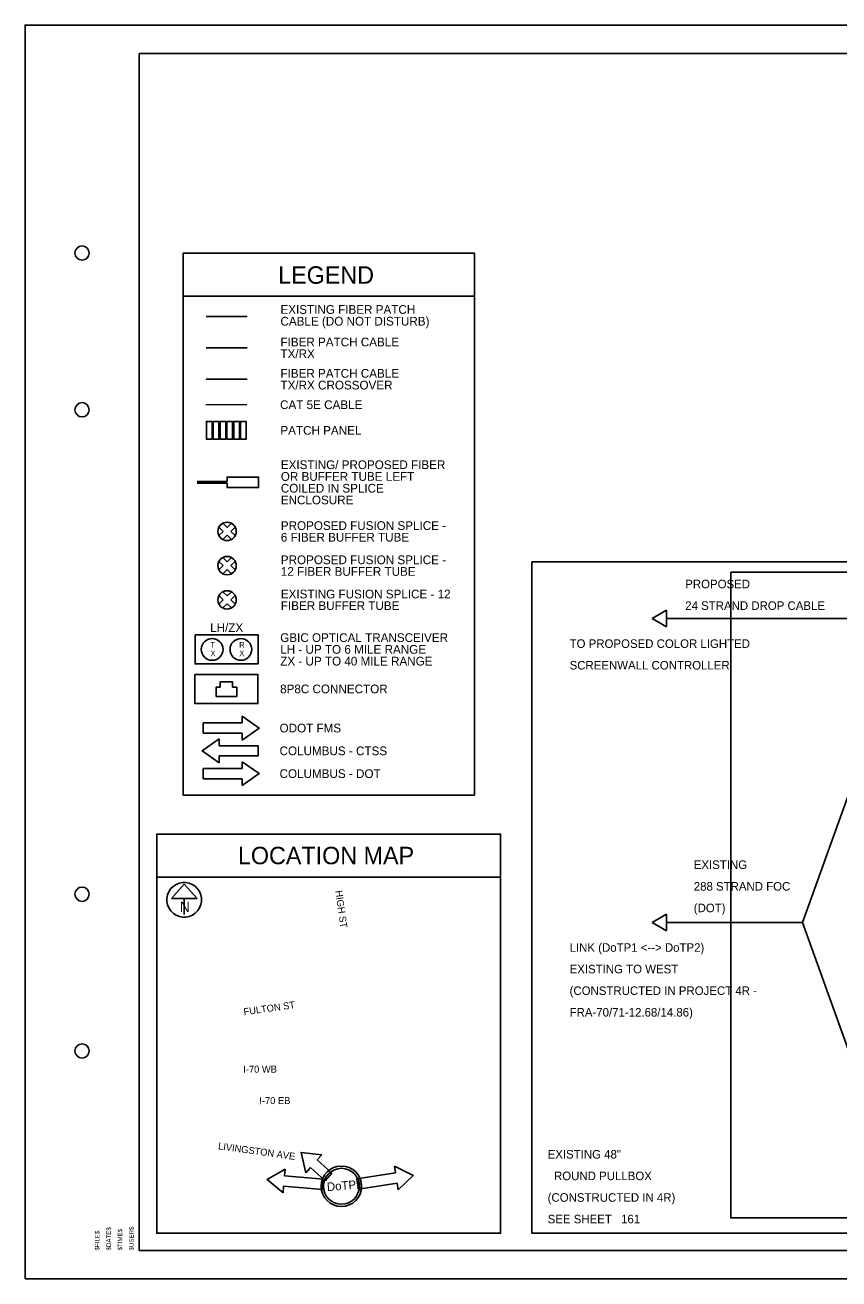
# Model space of a CAD drawing. Extents: x 1805893 to 1833564, y 708898 to 716199.
# Drawn here: x 1831322.5 to 1831608.1, y 714257.9 to 714697.9 of the extents above; entities that cross this region are included whole.
import ezdxf

# ---------------------------------------------------------------- set-up
doc = ezdxf.new("R2010")
doc.units = 0
for name, color, linetype in [('BR_P_Sub_Hidden', 7, 'Continuous'), ('BR_X_Slab_Object', 7, 'Continuous'), ('SH_Border', 7, 'Continuous'), ('SH_Cut_Line', 7, 'Continuous'), ('SH_Data', 7, 'Continuous'), ('SH_Text', 7, 'Continuous'), ('UT_X_Misc_Cells', 7, 'Continuous')]:
    doc.layers.add(name, color=color, linetype=linetype)

msp = doc.modelspace()

# ---------------------------------------------------------------- linework, layer by layer
at = {"layer": 'BR_P_Sub_Hidden'}
for points in [[(1831500.32, 714509.57), (1831957.51, 714509.57), (1831957.51, 714273.91), (1831500.32, 714273.91)], [(1831570.12, 714505.91), (1831894.14, 714505.91), (1831894.14, 714279.3), (1831570.12, 714279.3)]]:
    msp.add_lwpolyline(points, close=True, dxfattribs=at)
at = {"layer": 'SH_Border'}
msp.add_lwpolyline([(1831362.49, 714687.91), (1831992.49, 714687.91), (1831992.49, 714267.91), (1831362.49, 714267.91)], close=True, dxfattribs=at)
for centre in [(1831342.49, 714617.91), (1831342.49, 714562.91), (1831342.49, 714392.91), (1831342.49, 714337.91)]:
    msp.add_circle(centre, 2.5, dxfattribs=at)
at = {"layer": 'SH_Cut_Line'}
msp.add_lwpolyline([(1831322.49, 714257.91), (1832002.49, 714257.91), (1832002.49, 714697.91), (1831322.49, 714697.91)], close=True, dxfattribs=at)
at = {"layer": 'SH_Data'}
for p, q in [((1831386.09, 714595.63), (1831400.43, 714595.63)), ((1831386.09, 714584.63), (1831400.43, 714584.63)), ((1831392.03, 714520.23), (1831390.54, 714521.72)), ((1831390.54, 714521.72), (1831392.03, 714520.23)), ((1831393.39, 714521.58), (1831391.9, 714523.08)), ((1831393.39, 714521.58), (1831391.9, 714523.08)), ((1831393.39, 714521.58), (1831394.88, 714523.08)), ((1831394.88, 714523.08), (1831393.39, 714521.58)), ((1831394.75, 714520.23), (1831396.24, 714521.72)), ((1831394.75, 714520.23), (1831396.24, 714521.72)), ((1831390.54, 714518.74), (1831392.03, 714520.23)), ((1831392.03, 714520.23), (1831390.54, 714518.74)), ((1831391.9, 714517.38), (1831393.39, 714518.87)), ((1831391.9, 714517.38), (1831393.39, 714518.87)), ((1831394.88, 714517.38), (1831393.39, 714518.87)), ((1831393.39, 714518.87), (1831394.88, 714517.38)), ((1831396.24, 714518.74), (1831394.75, 714520.23)), ((1831396.24, 714518.74), (1831394.75, 714520.23)), ((1831392.03, 714508.22), (1831390.54, 714509.71)), ((1831392.03, 714508.22), (1831390.54, 714509.71)), ((1831390.54, 714506.73), (1831392.03, 714508.22)), ((1831390.54, 714506.73), (1831392.03, 714508.22)), ((1831393.39, 714509.57), (1831391.9, 714511.07)), ((1831391.9, 714511.07), (1831393.39, 714509.57)), ((1831393.39, 714509.57), (1831394.88, 714511.07)), ((1831393.39, 714509.57), (1831394.88, 714511.07)), ((1831394.75, 714508.22), (1831396.24, 714509.71)), ((1831396.24, 714509.71), (1831394.75, 714508.22)), ((1831396.24, 714506.73), (1831394.75, 714508.22)), ((1831394.75, 714508.22), (1831396.24, 714506.73)), ((1831391.9, 714505.37), (1831393.39, 714506.86)), ((1831393.39, 714506.86), (1831391.9, 714505.37)), ((1831394.88, 714505.37), (1831393.39, 714506.86)), ((1831394.88, 714505.37), (1831393.39, 714506.86)), ((1831393.39, 714497.57), (1831391.9, 714499.06)), ((1831391.9, 714499.06), (1831393.39, 714497.57)), ((1831393.39, 714497.57), (1831394.88, 714499.06)), ((1831393.39, 714497.57), (1831394.88, 714499.06)), ((1831392.03, 714496.21), (1831390.54, 714497.71)), ((1831392.03, 714496.21), (1831390.54, 714497.71)), ((1831390.54, 714494.72), (1831392.03, 714496.21)), ((1831390.54, 714494.72), (1831392.03, 714496.21)), ((1831391.9, 714493.37), (1831393.39, 714494.86)), ((1831393.39, 714494.86), (1831391.9, 714493.37)), ((1831394.88, 714493.37), (1831393.39, 714494.86)), ((1831394.88, 714493.37), (1831393.39, 714494.86)), ((1831394.75, 714496.21), (1831396.24, 714497.71)), ((1831396.24, 714497.71), (1831394.75, 714496.21)), ((1831396.24, 714494.72), (1831394.75, 714496.21)), ((1831394.75, 714496.21), (1831396.24, 714494.72)), ((1831542.51, 714489.68), (1831547.53, 714492.58)), ((1831547.53, 714486.78), (1831542.51, 714489.68)), ((1831547.53, 714492.58), (1831547.53, 714486.78)), ((1831613.14, 714489.68), (1831547.53, 714489.68)), ((1831398.67, 714453.02), (1831398.67, 714455.42)), ((1831384.93, 714453.02), (1831398.67, 714453.02)), ((1831384.93, 714449.42), (1831384.93, 714453.02)), ((1831398.67, 714449.42), (1831384.93, 714449.42)), ((1831390.6, 714447.42), (1831390.6, 714445.02)), ((1831398.67, 714447.02), (1831398.67, 714449.42)), ((1831390.6, 714445.02), (1831404.34, 714445.02)), ((1831404.34, 714441.42), (1831390.6, 714441.42)), ((1831390.6, 714441.42), (1831390.6, 714439.02)), ((1831404.34, 714445.02), (1831404.34, 714441.42)), ((1831384.93, 714437.02), (1831398.67, 714437.02)), ((1831384.93, 714433.42), (1831384.93, 714437.02)), ((1831398.67, 714437.02), (1831398.67, 714439.42)), ((1831398.67, 714433.42), (1831384.93, 714433.42)), ((1831398.67, 714431.02), (1831398.67, 714433.42)), ((1831547.53, 714385.89), (1831542.51, 714382.99)), ((1831547.53, 714380.09), (1831547.53, 714385.89)), ((1831542.51, 714382.99), (1831547.53, 714380.09)), ((1831595.29, 714382.99), (1831547.53, 714382.99))]:
    msp.add_line(p, q, dxfattribs=at)
for points in [[(1831377.93, 714617.86), (1831480.16, 714617.86), (1831480.16, 714602.75), (1831377.93, 714602.75)], [(1831480.16, 714617.86), (1831480.16, 714427.7), (1831377.93, 714427.7), (1831377.93, 714617.86)], [(1831388.1, 714558.81), (1831388.1, 714552.56), (1831386.14, 714552.56), (1831386.14, 714558.81)], [(1831390.49, 714558.81), (1831390.49, 714552.56), (1831388.53, 714552.56), (1831388.53, 714558.81)], [(1831392.89, 714558.81), (1831392.89, 714552.56), (1831390.93, 714552.56), (1831390.93, 714558.81)], [(1831395.28, 714558.81), (1831395.28, 714552.56), (1831393.32, 714552.56), (1831393.32, 714558.81)], [(1831397.68, 714558.81), (1831397.68, 714552.56), (1831395.72, 714552.56), (1831395.72, 714558.81)], [(1831400.07, 714558.81), (1831400.07, 714552.56), (1831398.11, 714552.56), (1831398.11, 714558.81)], [(1831382.14, 714483.95), (1831404.23, 714483.95), (1831404.23, 714473.7), (1831382.14, 714473.7)], [(1831382.08, 714470.07), (1831404.18, 714470.07), (1831404.18, 714459.82), (1831382.08, 714459.82)], [(1831489.36, 714414.04), (1831368.72, 714414.04), (1831368.72, 714398.93), (1831489.36, 714398.93)], [(1831489.36, 714398.93), (1831368.72, 714398.93), (1831368.72, 714414.04), (1831489.36, 714414.04)], [(1831489.36, 714398.93), (1831489.36, 714273.91), (1831368.72, 714273.91), (1831368.72, 714398.93)], [(1831489.36, 714398.93), (1831489.36, 714273.91), (1831368.72, 714273.91), (1831368.72, 714398.93)], [(1831489.36, 714398.93), (1831489.36, 714273.91), (1831368.72, 714273.91), (1831368.72, 714398.93)]]:
    msp.add_lwpolyline(points, close=True, dxfattribs=at)
for points in [[(1831400.46, 714573.63), (1831386.09, 714573.63), (1831386.09, 714573.63), (1831386.09, 714573.63)], [(1831385.95, 714564.69), (1831400.29, 714564.72), (1831400.29, 714564.72)], [(1831383.09, 714537.75), (1831383.09, 714537.45), (1831383.09, 714537.14), (1831393.38, 714537.14), (1831393.38, 714535.61), (1831404.43, 714535.61), (1831404.43, 714539.28), (1831393.38, 714539.28), (1831393.38, 714537.75), (1831383.09, 714537.75)], [(1831404.43, 714535.61), (1831404.43, 714539.28), (1831393.38, 714539.28), (1831393.38, 714537.75), (1831383.09, 714537.75), (1831383.09, 714537.45), (1831383.09, 714537.14), (1831393.38, 714537.14), (1831393.38, 714535.61), (1831404.43, 714535.61)], [(1831395.25, 714465.55), (1831396.76, 714465.55), (1831396.76, 714462.32), (1831389.49, 714462.32), (1831389.49, 714465.55), (1831391, 714465.55)], [(1831391, 714465.55), (1831391, 714467.46), (1831395.25, 714467.46), (1831395.25, 714465.55)], [(1831624.88, 714465.18), (1831595.29, 714382.99), (1831624.88, 714300.79)], [(1831624.88, 714465.18), (1831595.29, 714382.99), (1831624.88, 714300.79)], [(1831398.67, 714455.42), (1831404.67, 714451.22), (1831398.67, 714447.02)], [(1831390.6, 714439.02), (1831384.6, 714443.22), (1831390.6, 714447.42)], [(1831398.67, 714439.42), (1831404.67, 714435.22), (1831398.67, 714431.02)]]:
    msp.add_lwpolyline(points, dxfattribs=at)
for centre, radius in [((1831393.39, 714520.23), 3.22), ((1831393.39, 714508.22), 3.22), ((1831393.39, 714496.21), 3.22), ((1831388.14, 714478.83), 3.81), ((1831398.23, 714478.83), 3.81)]:
    msp.add_circle(centre, radius, dxfattribs=at)
for centre, start, end in [((1831393.39, 714520.23), 117.647, 152.353), ((1831393.39, 714520.23), 27.647, 62.353), ((1831393.39, 714520.23), 207.647, 242.353), ((1831393.39, 714520.23), 297.647, 332.353), ((1831393.39, 714508.22), 152.353, 207.647), ((1831393.39, 714508.22), 62.353, 117.647), ((1831393.39, 714508.22), 332.353, 27.647), ((1831393.39, 714508.22), 242.353, 297.647), ((1831393.39, 714496.21), 62.353, 117.647), ((1831393.39, 714496.21), 152.353, 207.647), ((1831393.39, 714496.21), 332.353, 27.647), ((1831393.39, 714496.21), 242.353, 297.647)]:
    msp.add_arc(centre, 3.22, start, end, dxfattribs=at)
at = {"layer": 'SH_Text'}
for p, q in [((1831378.33, 714396.42), (1831373.82, 714391.42)), ((1831382.83, 714391.42), (1831378.33, 714396.42)), ((1831373.82, 714391.42), (1831382.83, 714391.42)), ((1831378.33, 714391.42), (1831378.33, 714385.76)), ((1831426.62, 714301.44), (1831425.02, 714299.65)), ((1831413.75, 714296.47), (1831413.54, 714294.08)), ((1831422.63, 714296.96), (1831421.03, 714295.17)), ((1831427.76, 714292.39), (1831422.63, 714296.96)), ((1831425.02, 714299.65), (1831430.15, 714295.08)), ((1831452.52, 714295.12), (1831452.16, 714297.49)), ((1831413.54, 714294.08), (1831427.22, 714292.87)), ((1831427.22, 714292.87), (1831426.9, 714289.28)), ((1831430.15, 714295.08), (1831427.76, 714292.39)), ((1831438.95, 714293.01), (1831452.52, 714295.12)), ((1831439.5, 714289.46), (1831438.95, 714293.01)), ((1831413.22, 714290.49), (1831413.01, 714288.1)), ((1831426.9, 714289.28), (1831413.22, 714290.49)), ((1831453.08, 714291.56), (1831439.5, 714289.46)), ((1831453.44, 714289.19), (1831453.08, 714291.56))]:
    msp.add_line(p, q, dxfattribs=at)
for points in [[(1831421.03, 714295.17), (1831419.34, 714302.29), (1831426.62, 714301.44)], [(1831413.01, 714288.1), (1831407.4, 714292.82), (1831413.75, 714296.47)], [(1831452.16, 714297.49), (1831458.73, 714294.26), (1831453.44, 714289.19)]]:
    msp.add_lwpolyline(points, dxfattribs=at)
for radius in [7.11, 6.31]:
    msp.add_circle((1831433.49, 714290.41), radius, dxfattribs=at)
msp.add_arc((1831378.33, 714390.95), 6.08, 129.7798, 129.7633, dxfattribs=at)

# ---------------------------------------------------------------- texts
at = {"layer": 'BR_X_Slab_Object'}
for s, p in [('T', (1831387.53, 714479.43)), ('R', (1831397.63, 714479.43)), ('X', (1831387.53, 714476.43)), ('X', (1831397.63, 714476.43))]:
    msp.add_text(s, height=2, rotation=0.0475, dxfattribs=at).set_placement(p)
msp.add_text('161', height=3, dxfattribs=at).set_placement((1831531.63, 714277.41))
at = {"layer": 'SH_Data'}
for s, height, p in [('LEGEND', 6.119, (1831411.3, 714607.14)), ('EXISTING FIBER PATCH ', 3.0596, (1831412.11, 714596.58)), ('CABLE (DO NOT DISTURB)', 3.0596, (1831412.11, 714592.46)), ('FIBER PATCH CABLE', 3.0596, (1831412.11, 714585.16)), ('TX/RX', 3.06, (1831412.11, 714581.04)), ('TX/RX CROSSOVER', 3.0596, (1831412.11, 714570.04)), ('FIBER PATCH CABLE', 3.0596, (1831412.11, 714574.16)), ('CAT 5E CABLE', 3.0596, (1831411.97, 714563.16)), ('PATCH PANEL', 3.0596, (1831412.09, 714554.16)), ('EXISTING/ PROPOSED FIBER ', 3.0596, (1831412.23, 714542.1)), ('OR BUFFER TUBE LEFT ', 3.0596, (1831412.23, 714537.98)), ('COILED IN SPLICE ', 3.0596, (1831412.23, 714533.85)), ('ENCLOSURE', 3.06, (1831412.23, 714529.73)), ('PROPOSED FUSION SPLICE - ', 3.0596, (1831412.24, 714520.74)), ('6 FIBER BUFFER TUBE', 3.0596, (1831412.24, 714516.66)), ('PROPOSED FUSION SPLICE - ', 3.0596, (1831412.24, 714508.73)), ('12 FIBER BUFFER TUBE', 3.0596, (1831412.24, 714504.65)), ('PROPOSED', 3, (1831554.15, 714500.26)), ('EXISTING FUSION SPLICE - 12 ', 3.0596, (1831412.24, 714496.72)), ('FIBER BUFFER TUBE', 3.0596, (1831412.24, 714492.65)), ('24 STRAND DROP CABLE', 3, (1831554.15, 714492.68)), ('LH/ZX', 3.06, (1831387.45, 714484.95)), ('GBIC OPTICAL TRANSCEIVER', 3.0596, (1831412.03, 714481.42)), ('TO PROPOSED COLOR LIGHTED', 3, (1831513.57, 714479.35)), ('LH - UP TO 6 MILE RANGE', 3.0596, (1831412.03, 714477.3)), ('ZX - UP TO 40 MILE RANGE', 3.0596, (1831412.03, 714473.17)), ('SCREENWALL CONTROLLER', 3, (1831513.57, 714471.77)), ('8P8C CONNECTOR', 3.0596, (1831411.98, 714463.42)), ('ODOT FMS', 3.06, (1831411.8, 714449.69)), ('COLUMBUS - CTSS', 3.0596, (1831411.8, 714441.69)), ('COLUMBUS - DOT', 3.0596, (1831411.8, 714433.69)), ('LOCATION MAP', 6.1191, (1831397.18, 714403.43)), ('EXISTING', 3, (1831557.14, 714401.76)), ('288 STRAND FOC', 3, (1831557.14, 714394.18)), ('(DOT)', 3, (1831557.14, 714386.6)), ('LINK (DoTP1 <--> DoTP2)', 3, (1831513.57, 714372.71)), ('EXISTING TO WEST', 3, (1831513.57, 714365.14)), ('(CONSTRUCTED IN PROJECT 4R - ', 3, (1831513.57, 714357.56)), ('FRA-70/71-12.68/14.86)', 3, (1831513.57, 714349.98)), ('EXISTING 48" ', 3, (1831505.87, 714300.15)), ('  ROUND PULLBOX', 3, (1831505.87, 714292.57)), ('(CONSTRUCTED IN 4R)', 3, (1831505.87, 714284.99)), ('SEE SHEET', 3, (1831505.87, 714277.41))]:
    msp.add_text(s, height=height, dxfattribs=at).set_placement(p)
at = {"layer": 'SH_Text'}
for s, height, rotation, p in [('HIGH ST', 2.448, 278.061, (1831431.33, 714394.08)), ('N', 3.66, 360, (1831376.8, 714386.68)), ('FULTON ST', 2.448, 8.061, (1831399.34, 714350.41)), ('I-70 WB', 2.448, 0.3445, (1831399.05, 714330.24)), ('I-70 EB', 2.448, 0.3445, (1831404.69, 714319.23)), ('LIVINGSTON AVE', 2.4477, 352.086, (1831390.1, 714303.41)), ('DoTP2', 3, 5, (1831428.54, 714288.68))]:
    msp.add_text(s, height=height, rotation=rotation, dxfattribs=at).set_placement(p)
at = {"layer": 'UT_X_Misc_Cells'}
for s, p in [('$FILE$', (1831348.59, 714267.91)), ('$DATE$', (1831352.59, 714267.91)), ('$TIME$', (1831356.59, 714267.91)), ('$USER$', (1831360.59, 714267.91))]:
    msp.add_text(s, height=1.56, rotation=90, dxfattribs=at).set_placement(p)

doc.saveas('drawing.dxf')
